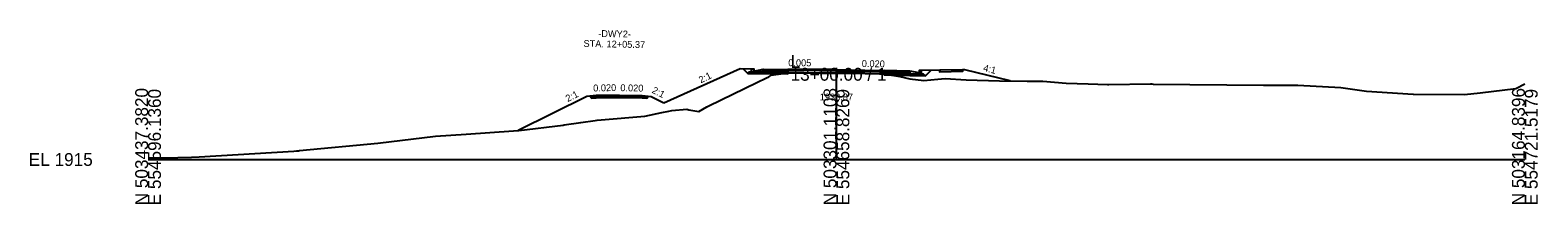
# Model space of a CAD drawing. Extents: x -26 to 4603, y -10 to 4703.
# Drawn here: x -25.7 to 302.8, y 1290.3 to 1328.2 of the extents above; entities that cross this region are included whole.
import ezdxf

# ---------------------------------------------------------------- set-up
doc = ezdxf.new("R2010")
doc.units = 0
for name, color, linetype in [('Default', 7, 'Continuous'), ('Exist Cross Section Cell', 7, 'Continuous'), ('Exist XS Ground Line', 7, 'Continuous'), ('Prop CMT Pvmt Course 1', 7, 'Continuous'), ('Prop CMT Pvmt Course 2', 7, 'Continuous'), ('Prop CMT Pvmt Course 3', 7, 'Continuous'), ('Prop CMT Pvmt Milling', 7, 'Continuous'), ('Prop CMT Pvmt Surface', 7, 'Continuous'), ('Prop CMT Shear Line', 7, 'Continuous'), ('Prop CMT Shld Paved Course 1', 7, 'Continuous'), ('Prop CMT Shld Paved Course 2', 7, 'Continuous'), ('Prop CMT Shld Paved Course 3', 7, 'Continuous'), ('Prop CMT Slope Grass', 7, 'Continuous'), ('Prop CMT Subgrade Earthwork', 7, 'Continuous'), ('Prop Conc 4in Sidewalk', 7, 'Continuous'), ('Prop Conc Curb and Gutter', 7, 'Continuous'), ('Prop Corridor Mesh Bottom', 7, 'Continuous'), ('Prop XS Finish Grade', 7, 'Continuous'), ('Prop XS Label Text', 7, 'Continuous'), ('Prop XS SE Text', 7, 'Continuous'), ('Prop XS Side Slope Text', 7, 'Continuous'), ('Prop XS SS Elevation Text', 7, 'Continuous'), ('Scratch_Level_9', 7, 'Continuous')]:
    doc.layers.add(name, color=color, linetype=linetype)

msp = doc.modelspace()

# ---------------------------------------------------------------- linework, layer by layer
at = {"layer": 'Exist Cross Section Cell'}
for p, q in [((150, 1300), (150, 1320)), ((0, 1300), (150, 1300)), ((150, 1300), (300, 1300))]:
    msp.add_line(p, q, dxfattribs=at)
at = {"layer": 'Exist XS Ground Line'}
msp.add_lwpolyline([(0, 1300.33), (3.51, 1300.39), (9.45, 1300.49), (11.13, 1300.59), (31.8, 1301.82), (32.33, 1301.86), (32.95, 1301.92), (33.02, 1301.93), (50.04, 1303.56), (62.66, 1305.1), (69.34, 1305.51), (79.61, 1306.28), (80.78, 1306.3), (90.48, 1307.49), (90.68, 1307.54), (94.29, 1308.07), (97.44, 1308.52), (97.89, 1308.61), (98.75, 1308.67), (108.26, 1309.49), (111.94, 1310.23), (113.51, 1310.57), (114.1, 1310.71), (117.39, 1311.01), (117.87, 1310.81), (120, 1310.47), (121.76, 1311.49), (122.18, 1311.68), (132.67, 1316.8), (134.77, 1317.83), (135.27, 1318.07), (135.95, 1318.46), (136.11, 1318.49), (136.26, 1318.5), (137.36, 1318.64), (139.52, 1318.9), (142.92, 1318.89), (146.38, 1318.88), (149.71, 1318.87), (153.09, 1318.82), (159.41, 1318.72), (160.27, 1318.69), (160.41, 1318.69), (160.7, 1318.65), (163.8, 1318.13), (165.97, 1317.64), (169.05, 1317.23), (172.13, 1317.56), (173.72, 1317.7), (178.25, 1317.36), (185.5, 1317.17), (191.56, 1317.09), (194.99, 1317.09), (200.07, 1316.69), (204.88, 1316.55), (209.09, 1316.36), (209.32, 1316.36), (218.45, 1316.49), (218.54, 1316.49), (218.75, 1316.49), (219.01, 1316.48), (243.04, 1316.22), (250.53, 1316.2), (259.89, 1315.68), (265.53, 1314.91), (275.7, 1314.28), (275.78, 1314.27), (286.88, 1314.22), (290.29, 1314.58), (298.02, 1315.48), (300, 1316.49)], dxfattribs=at)
at = {"layer": 'Prop CMT Pvmt Course 1'}
for points in [[(134, 1319.7), (139.43, 1319.67), (139.43, 1319.42), (139.43, 1319.42), (134, 1319.45), (134, 1319.45), (134, 1319.45), (134, 1319.7), (134, 1319.7)], [(149.71, 1319.62), (146.38, 1319.64), (146.38, 1319.64), (142.92, 1319.66), (142.92, 1319.66), (139.52, 1319.67), (139.52, 1319.67), (139.43, 1319.67), (139.43, 1319.67), (139.43, 1318.89), (139.43, 1318.89), (139.43, 1318.89), (139.52, 1318.9), (139.52, 1318.9), (142.92, 1318.89), (142.92, 1318.89), (146.38, 1318.88), (146.38, 1318.88), (149.71, 1318.87), (149.71, 1318.87), (150, 1318.87), (150, 1318.87), (150, 1319.62), (149.71, 1319.62), (149.71, 1319.62)], [(160.41, 1319.42), (160.41, 1318.69), (160.41, 1318.69), (160.27, 1318.69), (160.27, 1318.69), (159.41, 1318.72), (159.41, 1318.72), (159.41, 1318.72), (153.09, 1318.82), (153.09, 1318.82), (150, 1318.87), (150, 1318.87), (150, 1319.62), (153.09, 1319.56), (153.09, 1319.56), (159.41, 1319.44), (159.41, 1319.44), (159.41, 1319.44), (160.27, 1319.42), (160.27, 1319.42), (160.41, 1319.42)], [(160.41, 1319.42), (160.41, 1319.42), (160.41, 1319.17), (160.41, 1319.17), (160.41, 1319.17), (166, 1319.05), (166, 1319.05), (166, 1319.3), (160.41, 1319.42)], [(102.64, 1314.04), (97.64, 1313.94)], [(97.64, 1313.94), (97.64, 1313.69)], [(97.64, 1313.69), (102.64, 1313.79)], [(102.64, 1313.79), (102.64, 1314.04)], [(102.64, 1314.04), (107.64, 1313.94)], [(102.64, 1313.79), (102.64, 1314.04)], [(107.64, 1313.69), (102.64, 1313.79)], [(107.64, 1313.94), (107.64, 1313.69)]]:
    msp.add_lwpolyline(points, dxfattribs=at)
msp.add_lwpolyline([(102.64, 1313.79), (102.64, 1313.91), (102.64, 1313.91), (102.64, 1313.79)], close=True, dxfattribs=at)
msp.add_lwpolyline([(102.64, 1313.79), (102.64, 1313.91), (102.64, 1313.91), (102.64, 1313.79)], close=True, dxfattribs=at)
at = {"layer": 'Prop CMT Pvmt Course 2'}
for points in [[(134, 1319.45), (139.43, 1319.42), (139.43, 1319.09), (139.43, 1319.09), (134, 1319.12), (134, 1319.12), (134, 1319.12), (134, 1319.45), (134, 1319.45)], [(160.41, 1319.17), (160.41, 1319.17), (160.41, 1318.83), (160.41, 1318.83), (160.41, 1318.83), (166, 1318.72), (166, 1318.72), (166, 1319.05), (160.41, 1319.17)], [(102.64, 1313.79), (97.64, 1313.69)], [(97.64, 1313.69), (97.64, 1313.44)], [(97.64, 1313.44), (102.64, 1313.54)], [(102.64, 1313.54), (102.64, 1313.79)], [(102.64, 1313.54), (102.64, 1313.79)], [(102.64, 1313.79), (107.64, 1313.69)], [(107.64, 1313.44), (102.64, 1313.54)], [(107.64, 1313.69), (107.64, 1313.44)]]:
    msp.add_lwpolyline(points, dxfattribs=at)
at = {"layer": 'Prop CMT Pvmt Course 3'}
for points in [[(134, 1319.12), (139.43, 1319.09), (139.43, 1318.72), (139.43, 1318.72), (134, 1318.74), (134, 1318.74), (134, 1318.74), (134, 1319.12), (134, 1319.12)], [(160.41, 1318.83), (160.41, 1318.83), (160.41, 1318.46), (160.41, 1318.46), (160.41, 1318.46), (166, 1318.35), (166, 1318.35), (166, 1318.72), (160.41, 1318.83)], [(169, 1318.66), (166, 1318.72), (166, 1318.35), (166, 1318.35), (169.38, 1318.28), (169.38, 1318.28), (169.38, 1318.28), (169, 1318.66), (169, 1318.66)]]:
    msp.add_lwpolyline(points, dxfattribs=at)
at = {"layer": 'Prop CMT Pvmt Milling'}
for points in [[(150, 1318.87), (149.71, 1318.87), (149.71, 1318.87), (146.38, 1318.88), (146.38, 1318.88), (142.92, 1318.89), (142.92, 1318.89), (139.52, 1318.9), (139.52, 1318.9), (139.43, 1318.89), (139.43, 1318.89)], [(160.41, 1318.69), (160.27, 1318.69), (160.27, 1318.69), (159.41, 1318.72), (159.41, 1318.72), (159.41, 1318.72), (153.09, 1318.82), (153.09, 1318.82), (150, 1318.87)]]:
    msp.add_lwpolyline(points, dxfattribs=at)
at = {"layer": 'Prop CMT Pvmt Surface'}
for points in [[(102.64, 1314.04), (97.64, 1313.94)], [(102.64, 1314.04), (107.64, 1313.94)]]:
    msp.add_lwpolyline(points, dxfattribs=at)
at = {"layer": 'Prop CMT Shld Paved Course 1'}
for points in [[(97.64, 1313.94), (97.39, 1313.68)], [(97.39, 1313.68), (97.64, 1313.69)], [(97.64, 1313.69), (97.64, 1313.94)], [(107.64, 1313.94), (107.9, 1313.68)], [(107.64, 1313.69), (107.64, 1313.94)], [(107.9, 1313.68), (107.64, 1313.69)]]:
    msp.add_lwpolyline(points, dxfattribs=at)
at = {"layer": 'Prop CMT Shld Paved Course 2'}
for points in [[(149.71, 1319.37), (146.38, 1319.39), (146.38, 1319.39), (142.92, 1319.41), (142.92, 1319.41), (139.52, 1319.42), (139.52, 1319.42), (139.43, 1319.42), (139.43, 1319.42), (139.43, 1318.89), (139.43, 1318.89), (139.43, 1318.89), (139.52, 1318.9), (139.52, 1318.9), (142.92, 1318.89), (142.92, 1318.89), (146.38, 1318.88), (146.38, 1318.88), (149.71, 1318.87), (149.71, 1318.87), (150, 1318.87), (150, 1318.87), (150, 1319.37), (149.71, 1319.37), (149.71, 1319.37)], [(160.41, 1319.17), (160.41, 1318.69), (160.41, 1318.69), (160.27, 1318.69), (160.27, 1318.69), (159.41, 1318.72), (159.41, 1318.72), (159.41, 1318.72), (153.09, 1318.82), (153.09, 1318.82), (150, 1318.87), (150, 1318.87), (150, 1319.37), (153.09, 1319.31), (153.09, 1319.31), (159.41, 1319.19), (159.41, 1319.19), (159.41, 1319.19), (160.27, 1319.17), (160.27, 1319.17), (160.41, 1319.17)], [(97.64, 1313.69), (97.39, 1313.68), (96.89, 1313.67), (96.63, 1313.42)], [(96.63, 1313.42), (97.64, 1313.44)], [(97.64, 1313.44), (97.64, 1313.69)], [(107.64, 1313.69), (107.9, 1313.68), (108.4, 1313.67), (108.65, 1313.42)], [(107.64, 1313.44), (107.64, 1313.69)], [(108.65, 1313.42), (107.64, 1313.44)]]:
    msp.add_lwpolyline(points, dxfattribs=at)
at = {"layer": 'Prop CMT Shld Paved Course 3'}
msp.add_lwpolyline([(134, 1319.12), (134, 1319.12), (134, 1318.74), (134, 1318.74), (134, 1318.74), (130.7, 1318.76), (130.7, 1318.76), (131, 1319.13), (134, 1319.12)], dxfattribs=at)
at = {"layer": 'Prop CMT Slope Grass'}
for points in [[(97.64, 1313.94), (95.64, 1313.78), (80.68, 1306.3)], [(107.64, 1313.94), (109.64, 1313.78), (112.4, 1312.4)]]:
    msp.add_lwpolyline(points, dxfattribs=at)
at = {"layer": 'Prop CMT Subgrade Earthwork'}
for points in [[(129.62, 1319.84), (130.7, 1318.76), (130.7, 1318.76)], [(130.7, 1318.76), (130.7, 1318.76), (139.43, 1318.72)], [(169.38, 1318.28), (160.41, 1318.46), (160.41, 1318.46)], [(170.55, 1319.44), (169.38, 1318.28), (169.38, 1318.28)], [(97.64, 1313.44), (96.63, 1313.42), (96.23, 1313.83)], [(102.64, 1313.54), (97.64, 1313.44)], [(102.64, 1313.54), (107.64, 1313.44)], [(107.64, 1313.44), (108.65, 1313.42), (109.06, 1313.83)]]:
    msp.add_lwpolyline(points, dxfattribs=at)
at = {"layer": 'Prop Conc 4in Sidewalk'}
msp.add_lwpolyline([(172.5, 1319.48), (172.5, 1319.48), (172.49, 1319.15), (172.49, 1319.15), (172.49, 1319.15), (177.51, 1319.25), (177.51, 1319.25), (177.5, 1319.58), (172.5, 1319.48)], dxfattribs=at)
at = {"layer": 'Prop Conc Curb and Gutter'}
for points in [[(132, 1319.3), (134, 1319.7), (134, 1319.12), (134, 1319.12), (134, 1319.12), (131.5, 1319.13), (131.5, 1319.13), (131.5, 1319.8), (132, 1319.8), (132, 1319.8), (132, 1319.3), (132, 1319.3), (132, 1319.3)], [(168, 1318.9), (166, 1319.3), (166, 1318.72), (166, 1318.72), (168.5, 1318.67), (168.5, 1318.67), (168.5, 1318.67), (168.5, 1319.4), (168.5, 1319.4), (168, 1319.4), (168, 1318.9), (168, 1318.9), (168, 1318.9)]]:
    msp.add_lwpolyline(points, dxfattribs=at)
at = {"layer": 'Prop Corridor Mesh Bottom'}
msp.add_lwpolyline([(166, 1319.3), (166, 1319.05)], dxfattribs=at)
at = {"layer": 'Prop XS Finish Grade'}
for points in [[(112.4, 1312.4), (112.4, 1312.4), (129, 1319.85)], [(129, 1319.85), (131.5, 1319.8), (131.5, 1319.8)], [(172.5, 1319.48), (168.5, 1319.4), (168.5, 1319.4)], [(178, 1319.59), (177.5, 1319.58), (177.5, 1319.58)], [(187.82, 1317.14), (187.82, 1317.14), (178, 1319.59)]]:
    msp.add_lwpolyline(points, dxfattribs=at)
at = {"layer": 'Scratch_Level_9'}
msp.add_lwpolyline([(134, 1319.7), (134, 1319.45)], dxfattribs=at)

# ---------------------------------------------------------------- texts
at = {"layer": 'Default'}
msp.add_text('-', height=0.0001, dxfattribs=at).set_placement((0, 1300))
at = {"layer": 'Exist Cross Section Cell'}
for s, p in [('L', (140, 1320)), ('13+00.00 / 1', (140, 1317.2)), ('EL 1915', (-26, 1298.6))]:
    msp.add_text(s, height=2.8, dxfattribs=at).set_placement(p)
for s, p in [('N 503437.3820', (0, 1290)), ('E 554596.1360', (2.8, 1290)), ('N 503301.1108', (150, 1290)), ('E 554658.8269', (152.8, 1290)), ('N 503164.8396', (300, 1290)), ('E 554721.5179', (302.8, 1290))]:
    msp.add_text(s, height=2.8, rotation=90, dxfattribs=at).set_placement(p)
at = {"layer": 'Prop CMT Shear Line'}
for p in [(132, 1319.3), (134, 1319.7), (134, 1319.7), (150, 1319.62), (166, 1319.3), (166, 1319.3), (168, 1318.9), (172.5, 1319.48), (177.5, 1319.58), (178, 1319.59), (187.81, 1317.14), (93.18, 1307.91), (93.18, 1307.91)]:
    msp.add_text('X', height=0.0025, dxfattribs=at).set_placement(p)
at = {"layer": 'Prop XS Label Text'}
for s, rotation, p in [('0.005', 359.7304, (139.5, 1320.37)), ('0.020', 358.8542, (155.51, 1320.21)), ('4:1', 345.9638, (181.88, 1319.34))]:
    msp.add_text(s, height=1.5, rotation=rotation, dxfattribs=at).set_placement(p)
at = {"layer": 'Prop XS SE Text'}
for s, rotation, p in [('-DWY2-', 358.8542, (98.08, 1326.76)), ('STA. 12+05.37', 358.8542, (94.87, 1324.58)), ('0.020', 1.1458, (97.01, 1314.85)), ('0.020', 358.8542, (102.9, 1314.92))]:
    msp.add_text(s, height=1.5, rotation=rotation, dxfattribs=at).set_placement(p)
at = {"layer": 'Prop XS Side Slope Text'}
for rotation, p in [(26.5651, (120.45, 1316.59)), (26.5651, (91.44, 1312.52)), (333.4349, (109.65, 1314.63))]:
    msp.add_text('2:1', height=1.5, rotation=rotation, dxfattribs=at).set_placement(p)
at = {"layer": 'Prop XS SS Elevation Text'}
msp.add_text('1933.87', height=1.5, dxfattribs=at).set_placement((146.36, 1312.89))

doc.saveas('drawing.dxf')
